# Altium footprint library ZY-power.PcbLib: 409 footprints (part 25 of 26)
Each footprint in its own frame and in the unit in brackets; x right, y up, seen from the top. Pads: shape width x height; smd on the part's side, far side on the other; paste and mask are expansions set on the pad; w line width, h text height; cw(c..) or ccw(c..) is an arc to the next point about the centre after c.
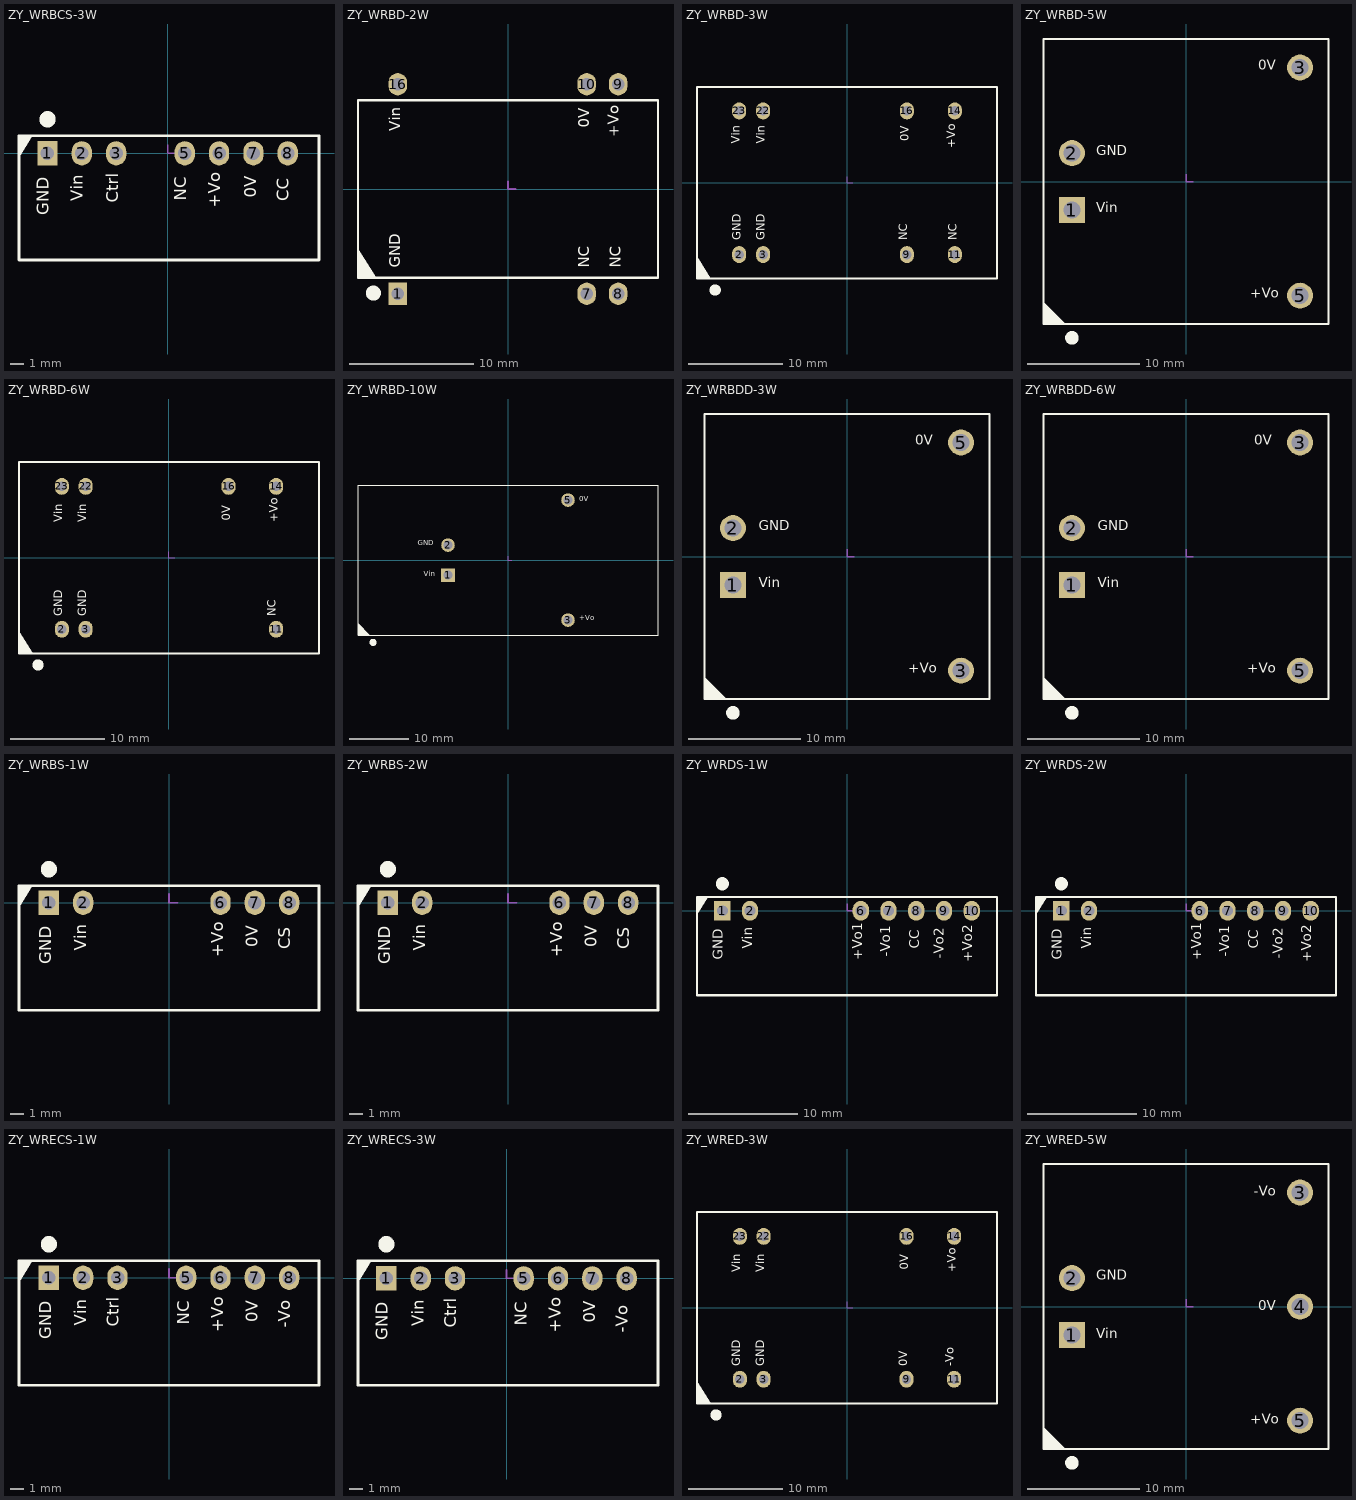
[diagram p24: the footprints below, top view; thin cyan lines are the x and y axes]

## ZY_WRBCS-3W [mm]
pads (7):
  rect 1.5x1.8 hole 1: 1(-8.89,0)
  oval 1.5x1.8 hole 1: 2(-6.35,0) 3(-3.81,0) 5(1.27,0) 6(3.81,0) 7(6.35,0) 8(8.89,0)
Top Overlay:
  circle w1: c-8.89,2.52 r0.1
  region: -10.998,-0.29 -10.998,1.295 -10.005,1.295
  lines w0.2: 11.201,-7.899 -10.998,-7.899 -10.998,1.295 11.201,1.295 11.201,-7.874
  text "GND" at -8.509,-4.572 h1.52
  text "Vin" at -5.969,-3.562 h1.52
  text "+Vo" at 4.191,-4.03 h1.52
  text "0V" at 6.858,-3.29 h1.52
  text "CC" at 9.271,-3.536 h1.52
  text "Ctrl" at -3.353,-3.646 h1.52
  text "NC" at 1.676,-3.501 h1.52
Bottom Overlay:
  lines w0.3: -7.62,-1.3 -7.62,1.3 ; -5.08,-1.3 -5.08,1.3 ; 2.54,-1.3 2.54,1.3 ; 5.08,-1.3 5.08,1.3 ; 7.62,-1.3 7.62,1.3
Mechanical 15:
  lines w0.127: 0,0.635 0,0 0.635,0

## ZY_WRBD-2W [mm]
pads (6):
  rect 1.5x1.8 hole 1: 1(-8.89,-8.45)
  oval 1.5x1.8 hole 1: 7(6.35,-8.45) 8(8.89,-8.45) 9(8.89,8.45) 10(6.35,8.45) 16(-8.89,8.45)
Top Overlay:
  circle w1: c-10.863,-8.4 r0.1
  region: -12.1,-4.845 -12.1,-7.175 -10.64,-7.175
  lines w0.2: -12.1,-7.175 -12.1,7.175 12.1,7.175 12.1,-7.175 -12.1,-7.175
  text "GND" at -8.382,-6.342 h1.52
  text "Vin" at -8.382,4.659 h1.52
  text "NC" at 6.858,-6.342 h1.52
  text "NC" at 9.398,-6.342 h1.52
  text "+Vo" at 9.271,4.191 h1.52
  text "0V" at 6.858,4.931 h1.52
Mechanical 15:
  lines w0.127: 0,0.635 0,0 0.635,0

## ZY_WRBD-3W [mm] "宽压输入隔离稳压单输出电源模块"
height 9.5
pads (8):
  oval 1.5x1.8 hole 1: 2(-11.43,-7.62) 3(-8.89,-7.62) 9(6.35,-7.62) 11(11.43,-7.62) 14(11.43,7.62) 16(6.35,7.62) 22(-8.89,7.62) 23(-11.43,7.62)
Top Overlay:
  circle w1: c-13.97,-11.375 r0.1
  region: -15.9,-7.82 -15.9,-10.15 -14.44,-10.15
  lines w0.2: -15.9,-10.15 15.9,-10.15 15.9,10.15 -15.9,10.15 -15.9,-10.15
  text "Vin" at -11.049,4.151 h1.52
  text "Vin" at -8.382,4.151 h1.52
  text "0V" at 6.858,4.423 h1.52
  text "+Vo" at 11.811,3.683 h1.52
  text "NC" at 11.938,-6.096 h1.52
  text "NC" at 6.731,-6.096 h1.52
  text "GND" at -8.382,-6.096 h1.52
  text "GND" at -10.922,-6.096 h1.52
Mechanical 15:
  lines w0.127: 0,0.635 0,0 0.635,0

## ZY_WRBD-5W [mm]
height 11.7
pads (4):
  rect 2.3x2.3 hole 1.5: 1(-10.16,-2.54)
  round 2.3 hole 1.5: 2(-10.16,2.54) 3(10.16,10.16) 5(10.16,-10.16)
Top Overlay:
  circle w1: c-10.16,-13.925 r0.1
  region: -12.7,-12.7 -10.725,-12.7 -12.7,-10.725
  lines w0.2: -12.7,-12.7 12.7,-12.7 12.7,12.7 -12.7,12.7 -12.7,-12.7
  text "GND" at -8.001,2.032 h1.52
  text "Vin" at -8.001,-3.048 h1.52
  text "+Vo" at 5.715,-10.668 h1.52
  text "0V" at 6.455,9.652 h1.52
Mechanical 15:
  lines w0.127: 0,0.635 0,0 0.635,0

## ZY_WRBD-6W [mm]
height 10.5
pads (7):
  oval 1.5x1.8 hole 1: 2(-11.43,-7.62) 3(-8.89,-7.62) 11(11.43,-7.62) 14(11.43,7.62) 16(6.35,7.62) 22(-8.89,7.62) 23(-11.43,7.62)
Top Overlay:
  circle w1: c-13.97,-11.425 r0.1
  region: -16,-7.87 -16,-10.2 -14.54,-10.2
  lines w0.2: -16,-10.2 -16,10.2 16,10.2 16,-10.2 -16,-10.2
  text "GND" at -11.049,-6.223 h1.52
  text "GND" at -8.509,-6.223 h1.52
  text "Vin" at -11.049,3.81 h1.52
  text "Vin" at -8.509,3.81 h1.52
  text "NC" at 11.684,-6.223 h1.52
  text "+Vo" at 11.938,3.81 h1.52
  text "0V" at 6.858,3.937 h1.52
Mechanical 15:
  lines w0.127: 0,0.635 0,0 0.635,0

## ZY_WRBD-10W [mm]
pads (4):
  rect 2.3x2.3 hole 1.5: 1(-10.16,-2.54)
  round 2.3 hole 1.5: 2(-10.16,2.54) 3(10.16,-10.16) 5(10.16,10.16)
Top Overlay:
  circle w1: c-22.86,-13.925 r0.1
  region: -25.4,-12.7 -23.425,-12.7 -25.4,-10.725
  lines w0.2: -25.4,-12.7 25.4,-12.7 25.4,12.7 -25.4,12.7 -25.4,-12.7
  text "Vin" at -14.231,-3.048 h1.52
  text "GND" at -15.241,2.159 h1.52
  text "0V" at 12.065,9.652 h1.52
  text "+Vo" at 12.065,-10.541 h1.52
Mechanical 15:
  lines w0.127: 0,0.635 0,0 0.635,0

## ZY_WRBDD-3W [mm]
height 11.7
pads (4):
  rect 2.3x2.3 hole 1.5: 1(-10.16,-2.54)
  round 2.3 hole 1.5: 2(-10.16,2.54) 3(10.16,-10.16) 5(10.16,10.16)
Top Overlay:
  circle w1: c-10.16,-13.925 r0.1
  region: -12.7,-12.7 -10.725,-12.7 -12.7,-10.725
  lines w0.2: -12.7,-12.7 12.7,-12.7 12.7,12.7 -12.7,12.7 -12.7,-12.7
  text "0V" at 6.074,9.652 h1.52
  text "+Vo" at 5.461,-10.668 h1.52
  text "Vin" at -7.874,-3.048 h1.52
  text "GND" at -7.875,2.032 h1.52
Mechanical 15:
  lines w0.127: 0,0.635 0,0 0.635,0

## ZY_WRBDD-6W [mm]
height 11.7
pads (4):
  rect 2.3x2.3 hole 1.5: 1(-10.16,-2.54)
  round 2.3 hole 1.5: 2(-10.16,2.54) 3(10.16,10.16) 5(10.16,-10.16)
Top Overlay:
  circle w1: c-10.16,-13.925 r0.1
  region: -12.7,-12.7 -10.725,-12.7 -12.7,-10.725
  lines w0.2: -12.7,-12.7 -12.7,12.7 12.7,12.7 12.7,-12.7 -12.7,-12.7
  text "+Vo" at 5.461,-10.668 h1.52
  text "GND" at -7.874,2.032 h1.52
  text "Vin" at -7.874,-3.048 h1.52
  text "0V" at 6.096,9.652 h1.52
Mechanical 15:
  lines w0.127: 0,0.635 0,0 0.635,0

## ZY_WRBS-1W [mm]
height 12.2
pads (5):
  rect 1.5x1.8 hole 1: 1(-8.89,0)
  oval 1.5x1.8 hole 1: 2(-6.35,0) 6(3.81,0) 7(6.35,0) 8(8.89,0)
Top Overlay:
  circle w1: c-8.89,2.475 r0.1
  region: -11.1,-0.336 -11.1,1.25 -10.106,1.25
  lines w0.2: -11.1,-7.95 -11.1,1.25 11.1,1.25 11.1,-7.95 -11.1,-7.95
  text "Vin" at -5.834,-3.562 h1.52
  text "+Vo" at 4.326,-4.03 h1.52
  text "0V" at 6.866,-3.29 h1.52
  text "CS" at 9.279,-3.443 h1.52
  text "GND" at -8.399,-4.572 h1.52
Mechanical 15:
  lines w0.127: 0,0.635 0,0 0.635,0
3D body "zhenjao01.stp": height 8.36, standoff -4.08, extent 8.19,-1.48 9.59,0.12
3D body "zhenjao01.stp": height 8.36, standoff -4.08, extent -9.59,-1.48 -8.19,0.12
3D body "zhenjao01.stp": height 8.36, standoff -4.08, extent -7.05,-1.48 -5.65,0.12
3D body "zhenjao01.stp": height 8.36, standoff -4.08, extent 3.11,-1.48 4.51,0.12
3D body "zhenjao01.stp": height 8.36, standoff -4.08, extent 5.65,-1.48 7.05,0.12
3D body: height 12.2, standoff 0, extent -11.1,-7.95 11.1,1.25

## ZY_WRBS-2W [mm]
height 12.2
pads (5):
  rect 1.5x1.8 hole 1: 1(-8.89,0)
  oval 1.5x1.8 hole 1: 2(-6.35,0) 6(3.81,0) 7(6.35,0) 8(8.89,0)
Top Overlay:
  circle w1: c-8.89,2.475 r0.1
  region: -11.1,-0.336 -11.1,1.25 -10.106,1.25
  lines w0.2: -11.1,-7.95 -11.1,1.25 11.1,1.25 11.1,-7.95 -11.1,-7.95
  text "Vin" at -5.834,-3.562 h1.52
  text "+Vo" at 4.326,-4.03 h1.52
  text "0V" at 6.866,-3.29 h1.52
  text "CS" at 9.279,-3.444 h1.52
  text "GND" at -8.399,-4.572 h1.52
Mechanical 15:
  lines w0.127: 0,0.635 0,0 0.635,0
3D body "zhenjao01.stp": height 8.36, standoff -4.08, extent 8.19,-1.48 9.59,0.12
3D body "zhenjao01.stp": height 8.36, standoff -4.08, extent -9.59,-1.48 -8.19,0.12
3D body "zhenjao01.stp": height 8.36, standoff -4.08, extent -7.05,-1.48 -5.65,0.12
3D body "zhenjao01.stp": height 8.36, standoff -4.08, extent 3.11,-1.48 4.51,0.12
3D body "zhenjao01.stp": height 8.36, standoff -4.08, extent 5.65,-1.48 7.05,0.12
3D body: height 12.2, standoff 0, extent -11.1,-7.95 11.1,1.25

## ZY_WRDS-1W [mm]
height 11.5
pads (7):
  rect 1.5x1.8 hole 1: 1(-11.43,0)
  oval 1.5x1.8 hole 1: 2(-8.89,0) 6(1.27,0) 7(3.81,0) 8(6.35,0) 9(8.89,0) 10(11.43,0)
Top Overlay:
  circle w1: c-11.43,2.475 r0.1
  region: -13.75,-0.336 -13.75,1.25 -12.756,1.25
  lines w0.2: -13.75,-7.75 -13.75,1.25 13.75,1.25 13.75,-7.75 -13.75,-7.75
  text "-Vo2" at 9.195,-4.387 h1.52
  text "+Vo2" at 11.811,-4.699 h1.52
  text "CC" at 6.96,-3.469 h1.52
  text "GND" at -11.049,-4.504 h1.52
  text "Vin" at -8.382,-3.494 h1.52
  text "+Vo1" at 1.702,-4.521 h1.52
  text "-Vo1" at 4.267,-4.209 h1.52
Mechanical 15:
  lines w0.127: 0,0.635 0,0 0.635,0

## ZY_WRDS-2W [mm]
height 11.5
pads (7):
  rect 1.5x1.8 hole 1: 1(-11.43,0)
  oval 1.5x1.8 hole 1: 2(-8.89,0) 6(1.27,0) 7(3.81,0) 8(6.35,0) 9(8.89,0) 10(11.43,0)
Top Overlay:
  circle w1: c-11.43,2.475 r0.1
  region: -13.75,-0.336 -13.75,1.25 -12.756,1.25
  lines w0.2: -13.75,-7.75 13.75,-7.75 13.75,1.25 -13.75,1.25 -13.75,-7.75
  text "-Vo1" at 4.267,-4.209 h1.52
  text "+Vo1" at 1.702,-4.521 h1.52
  text "Vin" at -8.382,-3.494 h1.52
  text "GND" at -11.049,-4.504 h1.52
  text "CC" at 6.96,-3.469 h1.52
  text "+Vo2" at 11.811,-4.699 h1.52
  text "-Vo2" at 9.195,-4.387 h1.52
Mechanical 15:
  lines w0.127: 0,0.635 0,0 0.635,0
3D body: height 11.5, standoff 0, extent -13.75,-7.75 13.75,1.25

## ZY_WRECS-1W [mm]
height 12.2
pads (7):
  rect 1.5x1.8 hole 1: 1(-8.89,0)
  oval 1.5x1.8 hole 1: 2(-6.35,0) 3(-3.81,0) 5(1.27,0) 6(3.81,0) 7(6.35,0) 8(8.89,0)
Top Overlay:
  circle w1: c-8.89,2.475 r0.1
  region: -11.1,-0.336 -11.1,1.25 -10.106,1.25
  lines w0.2: -11.1,-7.95 -11.1,1.25 11.1,1.25 11.1,-7.95 -11.1,-7.95
  text "Vin" at -5.834,-3.562 h1.52
  text "Ctrl" at -3.421,-3.646 h1.52
  text "NC" at 1.786,-3.501 h1.52
  text "+Vo" at 4.326,-4.03 h1.52
  text "0V" at 6.866,-3.29 h1.52
  text "-Vo" at 9.279,-3.718 h1.52
  text "GND" at -8.399,-4.572 h1.52
Mechanical 15:
  lines w0.127: 0,0.635 0,0 0.635,0
3D body "zhenjao01.stp": height 8.36, standoff -4.08, extent 8.19,-1.48 9.59,0.12
3D body "zhenjao01.stp": height 8.36, standoff -4.08, extent -9.59,-1.48 -8.19,0.12
3D body "zhenjao01.stp": height 8.36, standoff -4.08, extent -7.05,-1.48 -5.65,0.12
3D body "zhenjao01.stp": height 8.36, standoff -4.08, extent -4.51,-1.48 -3.11,0.12
3D body "zhenjao01.stp": height 8.36, standoff -4.08, extent 0.57,-1.48 1.97,0.12
3D body "zhenjao01.stp": height 8.36, standoff -4.08, extent 3.11,-1.48 4.51,0.12
3D body "zhenjao01.stp": height 8.36, standoff -4.08, extent 5.65,-1.48 7.05,0.12
3D body: height 12.2, standoff 0, extent -11.1,-7.95 11.1,1.25

## ZY_WRECS-3W [mm]
height 12.2
pads (7):
  rect 1.5x1.8 hole 1: 1(-8.89,0)
  oval 1.5x1.8 hole 1: 2(-6.35,0) 3(-3.81,0) 5(1.27,0) 6(3.81,0) 7(6.35,0) 8(8.89,0)
Top Overlay:
  circle w1: c-8.89,2.525 r0.1
  region: -10.99,-0.286 -10.99,1.3 -9.996,1.3
  lines w0.2: -10.99,-7.9 -10.99,1.3 11.21,1.3 11.21,-7.9 -10.99,-7.9
  text "GND" at -8.501,-4.572 h1.52
  text "Vin" at -5.834,-3.562 h1.52
  text "Ctrl" at -3.421,-3.646 h1.52
  text "NC" at 1.786,-3.501 h1.52
  text "+Vo" at 4.326,-4.03 h1.52
  text "0V" at 6.866,-3.29 h1.52
  text "-Vo" at 9.279,-4.03 h1.52
Mechanical 15:
  lines w0.127: 0,0.635 0,0 0.635,0

## ZY_WRED-3W [mm]
height 10.5
pads (8):
  oval 1.5x1.8 hole 1: 2(-11.43,-7.62) 3(-8.89,-7.62) 9(6.35,-7.62) 11(11.43,-7.62) 14(11.43,7.62) 16(6.35,7.62) 22(-8.89,7.62) 23(-11.43,7.62)
Top Overlay:
  circle w1: c-13.97,-11.425 r0.1
  region: -16,-7.87 -16,-10.2 -14.54,-10.2
  lines w0.2: -16,-10.2 -16,10.2 16,10.2 16,-10.2 -16,-10.2
  text "0V" at 6.731,-6.223 h1.52
  text "GND" at -11.049,-6.223 h1.52
  text "GND" at -8.509,-6.223 h1.52
  text "Vin" at -11.049,3.81 h1.52
  text "Vin" at -8.509,3.81 h1.52
  text "-Vo" at 11.684,-6.223 h1.52
  text "+Vo" at 11.938,3.81 h1.52
  text "0V" at 6.858,4.064 h1.52
Mechanical 15:
  lines w0.127: 0,0.635 0,0 0.635,0
3D body "zhen01.stp": height 6.09, standoff -4.41, extent 6.1,-7.87 6.6,-7.37
3D body "zhen01.stp": height 6.09, standoff -4.41, extent -9.14,-7.87 -8.64,-7.37
3D body "zhen01.stp": height 6.09, standoff -4.41, extent -11.68,-7.87 -11.18,-7.37
3D body "zhen01.stp": height 6.09, standoff -4.41, extent 11.18,-7.87 11.68,-7.37
3D body "zhen01.stp": height 6.09, standoff -4.41, extent 11.18,7.37 11.68,7.87
3D body "zhen01.stp": height 6.09, standoff -4.41, extent 6.1,7.37 6.6,7.87
3D body "zhen01.stp": height 6.09, standoff -4.41, extent -9.14,7.37 -8.64,7.87
3D body "zhen01.stp": height 6.09, standoff -4.41, extent -11.68,7.37 -11.18,7.87
3D body: height 11, standoff 0, extent -16,-10.2 16,10.2

## ZY_WRED-5W [mm]
height 11.7
pads (5):
  rect 2.3x2.3 hole 1.5: 1(-10.16,-2.54)
  round 2.3 hole 1.5: 2(-10.16,2.54) 3(10.16,10.16) 4(10.16,0) 5(10.16,-10.16)
Top Overlay:
  circle w1: c-10.16,-13.925 r0.1
  region: -12.7,-12.7 -10.725,-12.7 -12.7,-10.725
  lines w0.2: -12.7,-12.7 -12.7,12.7 12.7,12.7 12.7,-12.7 -12.7,-12.7
  text "-Vo" at 6.027,9.576 h1.52
  text "+Vo" at 5.715,-10.744 h1.52
  text "Vin" at -8.001,-3.15 h1.52
  text "GND" at -8.002,2.057 h1.52
  text "0V" at 6.455,-0.635 h1.52
Mechanical 15:
  lines w0.127: 0,0.635 0,0 0.635,0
